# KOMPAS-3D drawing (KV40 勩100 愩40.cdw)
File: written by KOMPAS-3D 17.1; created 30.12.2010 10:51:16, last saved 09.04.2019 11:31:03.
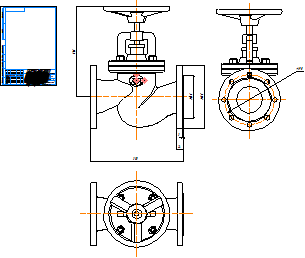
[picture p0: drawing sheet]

Title block, sheet 1: name: KV 40 Ду100; material: Внимание! Данный продукт является объектом авторского права ООО «Торговый Дом АДЛ». / Запрещается изменение, копирование, распространение / (в том числе путем копирования на другие сайты и ресурсы в Интернете) / или любое иное использование информации и объектов без предварительного / согласия правообладателя (ООО «Торговый Дом АДЛ»).; scale: 1:1; sheets: 1; organisation: ООО "Торговый дом АДЛ"; sheet format: A4; stored path: \\adlc.lan\data\АДЛ_ПКД\3D-модели\ADL production\Вентили ГРАНВЕНТ\KV40\KOMPAS 2D\KV 40 Ду100.cdw

Views: Спереди 1, Проекционный вид 2, Вид 5
Dimensions and other numbers on the sheet: 235; 162; 350; 3; 24; 340; 190; 1:1; 1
